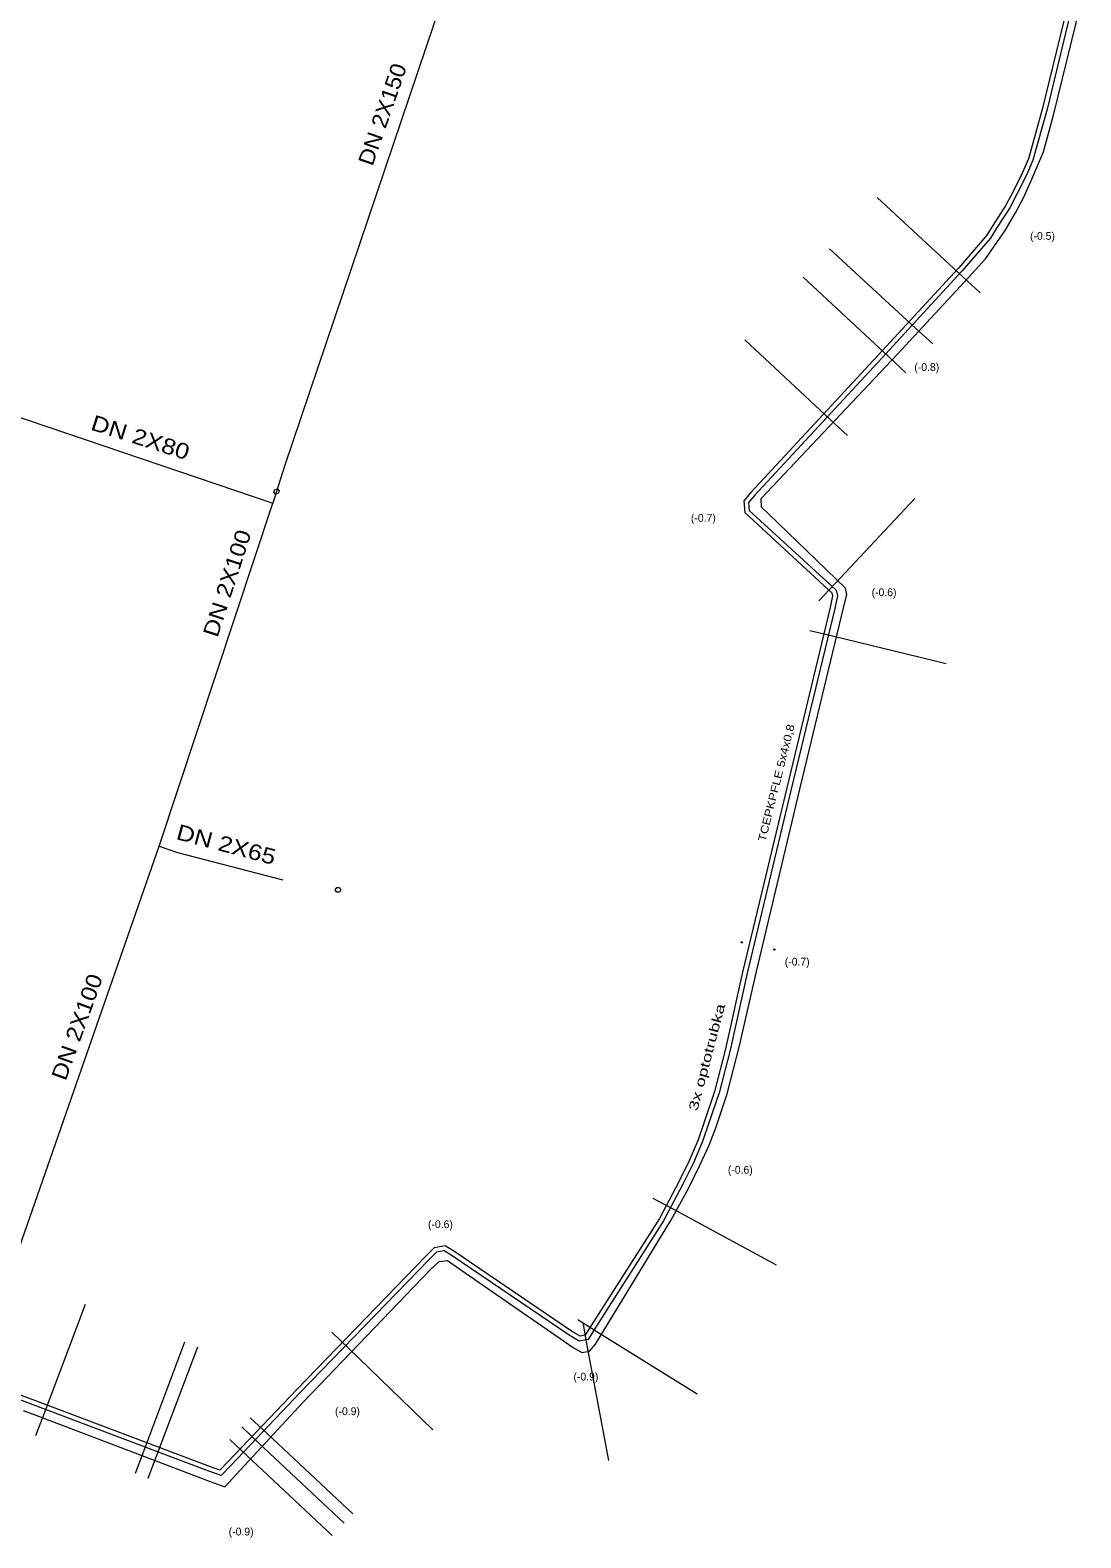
# Model space of a CAD drawing. Extents: x -725606 to -725269, y -977352 to -977136.
# Drawn here: x -725370.8 to -725303.4, y -977330.6 to -977233.9 of the extents above; entities that cross this region are included whole.
import ezdxf
from ezdxf.enums import TextEntityAlignment as Align

# ---------------------------------------------------------------- set-up
doc = ezdxf.new("R2010")
doc.units = 0
doc.header["$LTSCALE"] = 0.2
for name, color, linetype, lineweight in [('43', 7, 'Continuous', 13), ('47', 7, 'Continuous', 13), ('48', 7, 'Continuous', 13), ('63', 7, 'Continuous', 13)]:
    doc.layers.add(name, color=color, linetype=linetype, lineweight=lineweight)
doc.layers.add('46', color=7, linetype='Continuous')
doc.layers.add('7', color=7, linetype='Continuous')

msp = doc.modelspace()

# ---------------------------------------------------------------- linework, layer by layer
at = {"layer": '43'}
for points in [[(-725325.129, -977292.431), (-725325.17, -977292.444), (-725325.202, -977292.413), (-725325.191, -977292.369), (-725325.15, -977292.356), (-725325.118, -977292.387)], [(-725323.091, -977292.829), (-725323.049, -977292.816), (-725323.018, -977292.847), (-725323.029, -977292.891), (-725323.071, -977292.904), (-725323.102, -977292.873)]]:
    msp.add_lwpolyline(points, close=True, dxfattribs=at)
at = {"layer": '47'}
for points in [[(-725309.87, -977250.74), (-725310.97, -977249.72), (-725316.48, -977244.63)], [(-725318.38, -977259.9), (-725319.48, -977258.88), (-725324.96, -977253.76)], [(-725320.79, -977272.4), (-725319.33, -977272.75), (-725312.04, -977274.51)], [(-725330.86, -977308.8), (-725329.54, -977309.51), (-725322.94, -977313.08)], [(-725370.42, -977324.02), (-725369.89, -977322.62), (-725367.24, -977315.6)], [(-725364.04, -977326.44), (-725363.51, -977325.03), (-725360.86, -977318.02)], [(-725363.22, -977326.75), (-725362.69, -977325.34), (-725360.04, -977318.33)], [(-725357.22, -977323.47), (-725356.13, -977324.5), (-725350.66, -977329.63)], [(-725356.67, -977322.88), (-725355.57, -977323.91), (-725350.1, -977329.04)]]:
    msp.add_lwpolyline(points, dxfattribs=at)
at = {"layer": '48'}
for points in [[(-725312.91, -977254.03), (-725314.02, -977253.01), (-725319.52, -977247.92)], [(-725314.63, -977255.89), (-725315.73, -977254.86), (-725321.21, -977249.74)], [(-725320.22, -977270.49), (-725319.19, -977269.4), (-725314.05, -977263.94)], [(-725335.66, -977316.59), (-725334.38, -977317.39), (-725328.02, -977321.35)], [(-725335.35, -977316.78), (-725335.08, -977318.25), (-725333.71, -977325.63)], [(-725351.44, -977317.4), (-725350.36, -977318.44), (-725344.96, -977323.65)], [(-725357.98, -977324.28), (-725356.89, -977325.3), (-725351.42, -977330.44)]]:
    msp.add_lwpolyline(points, dxfattribs=at)
at = {"layer": '63'}
msp.add_line((-725362.524, -977286.239), (-725355.226, -977264.237), dxfattribs=at)
for points in [[(-725350.511, -977185.787), (-725349.36, -977186.525), (-725343.402, -977188.408), (-725330.746, -977191.568), (-725341.66, -977223.886), (-725354.485, -977261.861), (-725355.226, -977264.237)], [(-725303.79, -977231.61), (-725305.57, -977238.98), (-725306.48, -977242.25), (-725306.88, -977243.16), (-725307.49, -977244.38), (-725307.97, -977245.29), (-725308.81, -977246.6), (-725309.21, -977247.25), (-725311.04, -977249.36), (-725316.18, -977254.95), (-725324.34, -977263.75), (-725324.72, -977264.19), (-725324.67, -977264.7), (-725324.2, -977265.13), (-725319.68, -977269.29), (-725319.11, -977269.82), (-725319.02, -977270.17), (-725319.19, -977271), (-725321.98, -977282.57), (-725324.81, -977294.37), (-725325.9, -977299.3), (-725326.61, -977302.05), (-725327.28, -977304.03), (-725327.68, -977305.16), (-725328.26, -977306.54), (-725328.93, -977307.9), (-725330.18, -977310.26), (-725334.7, -977317.37), (-725335.01, -977317.86), (-725335.58, -977317.97), (-725336.23, -977317.58), (-725343.73, -977312.49), (-725344.23, -977312.17), (-725344.74, -977312.26), (-725345.23, -977312.76), (-725353.48, -977321.27), (-725357.9, -977325.91), (-725358.55, -977326.59), (-725359.33, -977326.3), (-725370.76, -977321.99), (-725381.91, -977317.79)], [(-725304.081, -977231.536), (-725305.86, -977238.905), (-725306.763, -977242.149), (-725307.152, -977243.032), (-725307.757, -977244.243), (-725308.229, -977245.139), (-725309.064, -977246.44), (-725309.453, -977247.072), (-725311.264, -977249.16), (-725316.4, -977254.746), (-725324.564, -977263.55), (-725325.031, -977264.091), (-725324.957, -977264.844), (-725324.403, -977265.351), (-725319.884, -977269.51), (-725319.379, -977269.98), (-725319.328, -977270.178), (-725319.483, -977270.935), (-725322.272, -977282.5), (-725325.102, -977294.303), (-725326.192, -977299.23), (-725326.898, -977301.964), (-725327.564, -977303.932), (-725327.96, -977305.052), (-725328.533, -977306.415), (-725329.197, -977307.763), (-725330.44, -977310.109), (-725334.953, -977317.209), (-725335.194, -977317.59), (-725335.524, -977317.654), (-725336.068, -977317.327), (-725343.565, -977312.239), (-725344.167, -977311.854), (-725344.887, -977311.981), (-725345.445, -977312.551), (-725353.696, -977321.062), (-725358.117, -977325.703), (-725358.63, -977326.24), (-725359.225, -977326.019), (-725370.654, -977321.709), (-725381.802, -977317.51)], [(-725307.06, -977244.61), (-725306.55, -977243.47), (-725305.81, -977241.72), (-725305.17, -977239.35), (-725303.41, -977232.22)], [(-725371.23, -977322.41), (-725370.43, -977322.72), (-725359.25, -977326.96), (-725358.31, -977327.32), (-725357.58, -977326.52), (-725353.31, -977321.9), (-725345.14, -977313.4), (-725344.55, -977312.87), (-725344.03, -977312.8), (-725343.44, -977313.2), (-725335.96, -977318.38), (-725335.41, -977318.69), (-725334.91, -977318.6), (-725334.54, -977318.16), (-725329.7, -977310.24), (-725328.54, -977308.14), (-725327.82, -977306.64), (-725327.24, -977305.4), (-725326.81, -977304.3), (-725326.09, -977302.12), (-725325.3, -977299.03), (-725324.2, -977294.26), (-725321.41, -977282.5), (-725318.6, -977270.86), (-725318.42, -977270.11), (-725318.5, -977269.69), (-725319.1, -977269.12), (-725323.45, -977264.93), (-725323.88, -977264.5), (-725323.91, -977263.94), (-725323.52, -977263.53), (-725315.2, -977254.7), (-725310.61, -977249.77), (-725309.53, -977248.57), (-725309, -977247.81), (-725308.26, -977246.75), (-725307.61, -977245.63), (-725307.06, -977244.61)], [(-725392.672, -977283.251), (-725395.077, -977282.248), (-725390.042, -977266.604), (-725385.627, -977253.982), (-725384.245, -977254.395), (-725355.226, -977264.237)], [(-725373.641, -977318.016), (-725372.809, -977315.746), (-725362.524, -977286.239), (-725361.335, -977286.635), (-725354.58, -977288.386)]]:
    msp.add_lwpolyline(points, dxfattribs=at)
for points in [[(-725354.88, -977263.625), (-725355.051, -977263.663), (-725355.165, -977263.53), (-725355.107, -977263.359), (-725354.937, -977263.321), (-725354.823, -977263.454)], [(-725350.951, -977288.882), (-725350.861, -977289.032), (-725350.951, -977289.182), (-725351.131, -977289.182), (-725351.221, -977289.032), (-725351.131, -977288.882)]]:
    msp.add_lwpolyline(points, close=True, dxfattribs=at)

# ---------------------------------------------------------------- texts
at = {"layer": '46'}
for s, p in [('(-0.5)', (-725305.87, -977247.35)), ('(-0.8)', (-725313.29, -977255.76)), ('(-0.7)', (-725327.62, -977265.43)), ('(-0.6)', (-725316.03, -977270.2)), ('(-0.7)', (-725321.6, -977293.89)), ('(-0.6)', (-725325.25, -977307.23)), ('(-0.6)', (-725344.48, -977310.72)), ('(-0.9)', (-725335.15, -977320.49)), ('(-0.9)', (-725350.44, -977322.71)), ('(-0.9)', (-725357.26, -977330.43))]:
    msp.add_text(s, height=0.5, dxfattribs=at).set_placement(p, align=Align.CENTER)
at = {"layer": '63'}
for s, height, rotation, width, p in [('DN 2X150', 1, 70.932, 1.1, (-725347.7259, -977239.4668)), ('DN 2X80', 1, 342.342, 1.2, (-725363.8672, -977260.4969)), ('DN 2X100', 1, 72.021, 1.15, (-725357.6843, -977269.5258)), ('TCEPKPFLE 5x4x0,8', 0.5, 75.917, 1.2, (-725322.6985, -977282.2298)), ('DN 2X65', 1, 345.092, 1.2, (-725358.3381, -977286.6054)), ('DN 2X100', 1, 70.187, 1.15, (-725367.31, -977297.989))]:
    msp.add_text(s, height=height, rotation=rotation, dxfattribs=dict(at, width=width)).set_placement(p, align=Align.CENTER)
at = {"layer": '7', "width": 1.45}
msp.add_text('3x optotrubka', height=0.6, rotation=75.287, dxfattribs=at).set_placement((-725327.1061, -977299.8357), align=Align.CENTER)

doc.saveas('drawing.dxf')
